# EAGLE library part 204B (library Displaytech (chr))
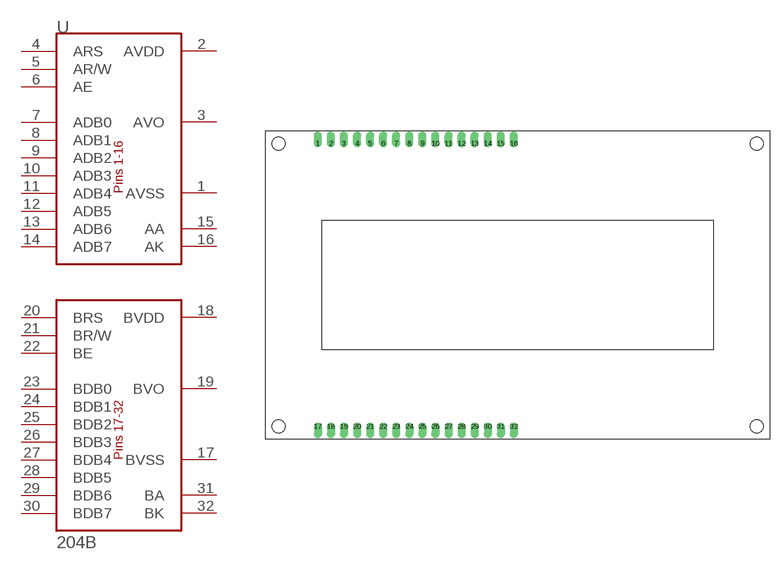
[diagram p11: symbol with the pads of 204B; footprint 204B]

Designator prefix -

## 204B  [204B]
1  AVSS  pwr
2  AVDD  pwr
3  AVO  in
4  ARS
5  AR/W
6  AE
7  ADB0
8  ADB1
9  ADB2
10  ADB3
11  ADB4
12  ADB5
13  ADB6
14  ADB7
15  AA  pwr
16  AK  pwr
17  BVSS  pwr
18  BVDD  pwr
19  BVO  in
20  BRS
21  BR/W
22  BE
23  BDB0
24  BDB1
25  BDB2
26  BDB3
27  BDB4
28  BDB5
29  BDB6
30  BDB7
31  BA  pwr
32  BK  pwr

## Footprint 204B (pad centres in mm)
drill 1.016 offset: 1 0,55; 2 2.54,55; 3 5.08,55; 4 7.62,55; 5 10.16,55; 6 12.7,55; 7 15.24,55; 8 17.78,55; 9 20.32,55; 10 22.86,55; 11 25.4,55; 12 27.94,55; 13 30.48,55; 14 33.02,55; 15 35.56,55; 16 38.1,55; 17 0,0; 18 2.54,0; 19 5.08,0; 20 7.62,0; 21 10.16,0; 22 12.7,0; 23 15.24,0; 24 17.78,0; 25 20.32,0; 26 22.86,0; 27 25.4,0; 28 27.94,0; 29 30.48,0; 30 33.02,0; 31 35.56,0; 32 38.1,0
